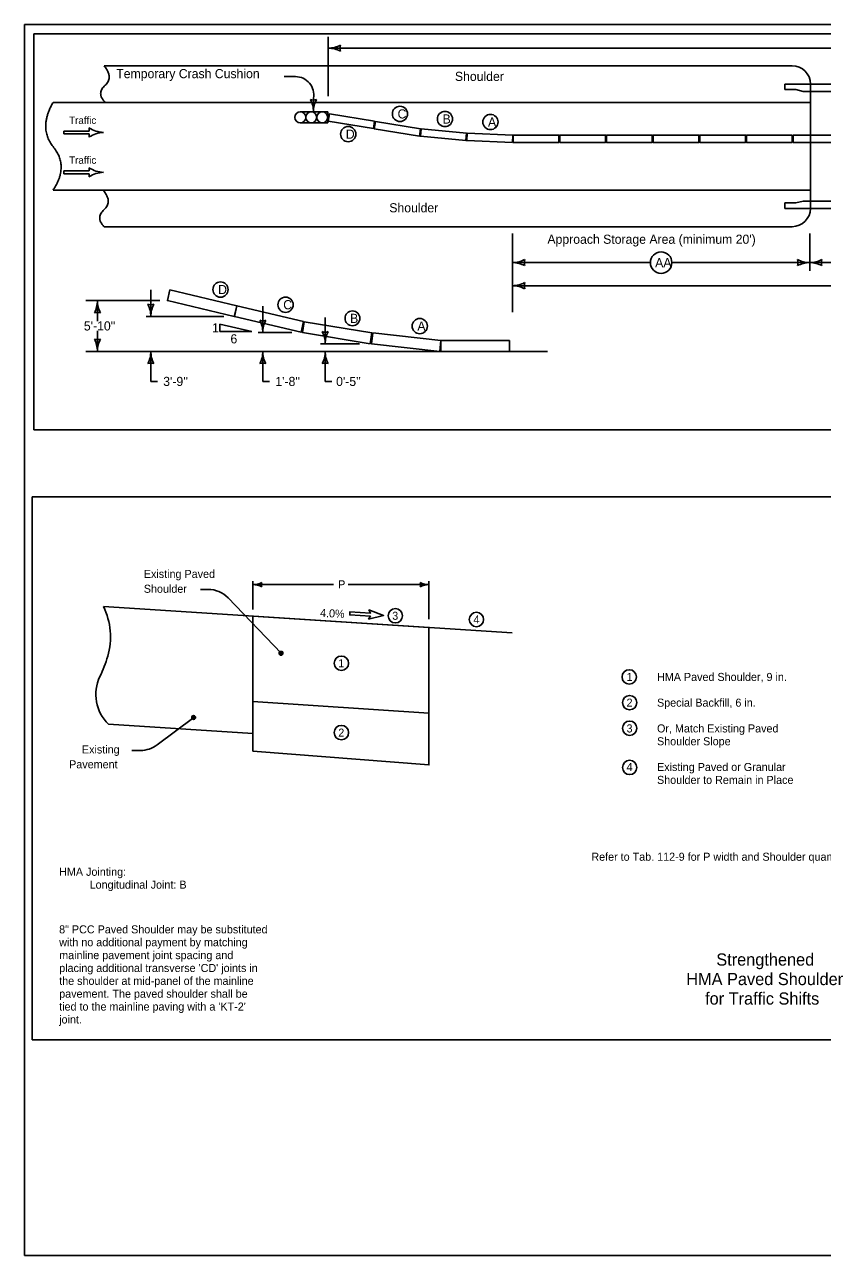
# Model space of a CAD drawing. Extents: x 10133 to 81668, y 7924 to 12229.
# Drawn here: x 13733 to 15041, y 7924 to 9944 of the extents above; entities that cross this region are included whole.
import ezdxf

# ---------------------------------------------------------------- set-up
doc = ezdxf.new("R2010")
doc.units = 0
for name, color, linetype in [('dsnTextFinalPlan', 7, 'Continuous'), ('Level 11', 7, 'Continuous'), ('Level 14', 7, 'Continuous'), ('Level 2', 7, 'Continuous'), ('Level 20', 7, 'Continuous'), ('Level 8', 7, 'Continuous'), ('Level 9', 7, 'Continuous'), ('SheetBorder', 7, 'Continuous'), ('SheetText', 7, 'Continuous')]:
    doc.layers.add(name, color=color, linetype=linetype)

msp = doc.modelspace()

# ---------------------------------------------------------------- linework, layer by layer
at = {"layer": 'dsnTextFinalPlan'}
for p, q in [((14395.5, 8954.6), (14107, 8973.3)), ((14107, 8973.3), (14107, 8832.9)), ((14395.5, 8814.2), (14395.5, 8954.6)), ((14107, 8832.9), (14395.5, 8814.2))]:
    msp.add_line(p, q, dxfattribs=at)
msp.add_circle((14252, 8895.9), 11.8, dxfattribs=at)
at = {"layer": 'Level 11'}
for p, q in [((14230.5, 9924.1), (14230.5, 9826.6)), ((14230.5, 9905.4), (15109, 9905.4)), ((13862.8, 9876.4), (14991.3, 9876.4)), ((14176.7, 9858.7), (14158, 9858.7)), ((15021.3, 9846.4), (14979.3, 9846.4)), ((14979.3, 9846.4), (14979.3, 9837.4)), ((14979.3, 9837.4), (14997.3, 9837.4)), ((15009.3, 9834.4), (14997.3, 9837.4)), ((15021.3, 9846.4), (15021.3, 9642.4)), ((15021.3, 9846.4), (15167.3, 9846.4)), ((14206.2, 9823.4), (14206.2, 9800.9)), ((15021.3, 9834.4), (15009.3, 9834.4)), ((15021.3, 9834.4), (15167.3, 9834.4)), ((13779.2, 9816.4), (15021.3, 9816.4)), ((14184.6, 9800.9), (14229.6, 9800.9)), ((14229.6, 9800.9), (14229.6, 9782.8)), ((14229.6, 9782.8), (14184.6, 9782.8)), ((14228.4, 9788.6), (14229.7, 9788.3)), ((14230.1, 9784.9), (14230.1, 9784.9)), ((13838.1, 9769.3), (13796.8, 9769.3)), ((13796.8, 9769.3), (13796.8, 9764.8)), ((13796.8, 9764.8), (13838.1, 9764.8)), ((13838.1, 9774.5), (13838.1, 9769.3)), ((13838.1, 9764.8), (13838.1, 9759.5)), ((13862, 9767), (13862, 9767)), ((13838.1, 9703.8), (13796.8, 9703.8)), ((13796.8, 9703.8), (13796.8, 9699.3)), ((13796.8, 9699.3), (13838.1, 9699.3)), ((13838.1, 9709.1), (13838.1, 9703.8)), ((13838.1, 9699.3), (13838.1, 9694.1)), ((13862, 9701.6), (13862, 9701.6)), ((13779.2, 9672.4), (15021.3, 9672.4)), ((14979.3, 9651.4), (14997.3, 9651.4)), ((14979.3, 9642.4), (14979.3, 9651.4)), ((15021.3, 9642.4), (14979.3, 9642.4)), ((15009.3, 9654.4), (14997.3, 9651.4)), ((15021.3, 9654.4), (15009.3, 9654.4)), ((15021.3, 9654.4), (15167.3, 9654.4)), ((15021.3, 9642.4), (15167.3, 9642.4)), ((13862.8, 9612.4), (14991.3, 9612.4)), ((14532.6, 9601.2), (14532.6, 9472)), ((15020.1, 9601.2), (15020.1, 9539.9)), ((14532.6, 9553.4), (14758.7, 9553.4)), ((14794, 9553.4), (15020.1, 9553.4)), ((15020.1, 9553.4), (15163.3, 9553.4)), ((14532.6, 9515.5), (15123.4, 9515.5)), ((13939.5, 9508.5), (13939.5, 9465)), ((13954.1, 9491), (13832.9, 9491)), ((13851.9, 9491), (13851.9, 9457.5)), ((14123.1, 9482.1), (14123.1, 9438.6)), ((14059, 9465), (13931.8, 9465)), ((14225.5, 9463.5), (14225.5, 9420.1)), ((13851.9, 9441.2), (13851.9, 9407.7)), ((14170.9, 9438.6), (14115.3, 9438.6)), ((14281.8, 9420.1), (14217.7, 9420.1)), ((14590.3, 9407.7), (13832.9, 9407.7)), ((13939.5, 9407.7), (13939.5, 9358.5)), ((14123.1, 9407.7), (14123.1, 9358.5)), ((14225.5, 9407.7), (14225.5, 9380.8)), ((14225.5, 9380.8), (14225.5, 9358.5)), ((13939.5, 9358.5), (13950.7, 9358.5)), ((14123.1, 9358.5), (14134.3, 9358.5)), ((14225.5, 9358.5), (14236.6, 9358.5))]:
    msp.add_line(p, q, dxfattribs=at)
for points in [[(14306.4, 9785.3), (14232.4, 9797.4), (14230.5, 9785.6), (14304.5, 9773.4)], [(14381.9, 9772.9), (14307.9, 9785), (14306, 9773.2), (14380, 9761)], [(14457.3, 9765.7), (14382.7, 9772.8), (14381.5, 9760.8), (14456.2, 9753.7)], [(14533.1, 9762.7), (14458.2, 9765.7), (14457.7, 9753.7), (14532.6, 9750.7)], [(14533.8, 9762.7), (14608.8, 9762.7), (14608.8, 9750.7), (14533.8, 9750.7)], [(14610.3, 9762.7), (14685.3, 9762.7), (14685.3, 9750.7), (14610.3, 9750.7)], [(14686.8, 9762.7), (14761.8, 9762.7), (14761.8, 9750.7), (14686.8, 9750.7)], [(14763.3, 9762.7), (14838.3, 9762.7), (14838.3, 9750.7), (14763.3, 9750.7)], [(14839.8, 9762.7), (14914.8, 9762.7), (14914.8, 9750.7), (14839.8, 9750.7)], [(14916.3, 9762.7), (14991.3, 9762.7), (14991.3, 9750.7), (14916.3, 9750.7)], [(14992.8, 9762.7), (15067.8, 9762.7), (15067.8, 9750.7), (14992.8, 9750.7)], [(14080.3, 9482.6), (13970.9, 9508.5), (13966.7, 9491), (14076.2, 9465.1)], [(14190.1, 9456.6), (14080.6, 9482.5), (14076.5, 9465), (14186, 9439.1)], [(14302.2, 9437.9), (14191.2, 9456.4), (14188.3, 9438.6), (14299.2, 9420.2)], [(14415.3, 9425.6), (14303.5, 9437.9), (14301.5, 9420.1), (14413.3, 9407.7)], [(14527.8, 9425.7), (14415.3, 9425.7), (14415.3, 9407.7), (14527.8, 9407.7)]]:
    msp.add_lwpolyline(points, close=True, dxfattribs=at)
for centre, radius in [((14184.6, 9791.8), 9), ((14184.6, 9791.8), 9), ((14202.6, 9791.8), 9), ((14202.6, 9791.8), 9), ((14220.6, 9791.8), 9), ((14220.6, 9791.8), 9), ((14348.1, 9797.5), 12.5), ((14421.9, 9789.1), 12.5), ((14263.2, 9764.3), 12.5), ((14496.4, 9784.2), 12.5), ((14776.4, 9553.4), 17.6), ((14053.8, 9509.2), 12.5), ((14160.5, 9484.3), 12.5), ((14270.2, 9461.9), 12.2), ((14380.5, 9449.2), 12.5)]:
    msp.add_circle(centre, radius, dxfattribs=at)
for centre, radius, start, end in [((14230.5, 9947.9), 42.5, 270, 298.0725), ((14230.5, 9862.9), 42.5, 61.9275, 90), ((14266.1, 9905.4), 16.4, 162.2666, 197.7334), ((14176.7, 9828.7), 30, 349.6463, 90), ((14991.3, 9846.4), 30, 0, 90), ((14206.2, 9836.5), 16.4, 252.2666, 287.7333), ((14163.7, 9800.9), 42.5, 360, 28.0725), ((14248.7, 9800.9), 42.5, 151.9275, 180), ((13864, 9815.4), 48.4, 237.618, 267.648), ((13864, 9718.7), 48.4, 92.352, 122.382), ((13864, 9749.9), 48.4, 237.618, 267.648), ((13864, 9653.3), 48.4, 92.352, 122.382), ((14991.3, 9642.4), 30, 270, 360), ((14532.6, 9595.9), 42.5, 270, 298.0725), ((14568.3, 9553.4), 16.4, 162.2666, 197.7334), ((14984.5, 9553.4), 16.4, 342.2666, 17.7333), ((15020.1, 9595.9), 42.5, 241.9275, 270), ((15020.1, 9595.9), 42.5, 270, 298.0725), ((15055.8, 9553.4), 16.4, 162.2666, 197.7334), ((14532.6, 9510.9), 42.5, 61.9275, 90), ((15020.1, 9510.9), 42.5, 90, 118.0725), ((15020.1, 9510.9), 42.5, 61.9275, 90), ((14532.6, 9558), 42.5, 270, 298.0725), ((14532.6, 9473), 42.5, 61.9275, 90), ((14568.3, 9515.5), 16.4, 162.2666, 197.7334), ((13809.4, 9491), 42.5, 331.9275, 0), ((13894.4, 9491), 42.5, 180, 208.0725), ((13939.5, 9500.7), 16.4, 252.2666, 287.7334), ((13897, 9465), 42.5, 0, 28.0725), ((13982, 9465), 42.5, 151.9275, 180), ((13851.9, 9455.4), 16.4, 72.2666, 107.7334), ((14123.1, 9474.3), 16.4, 252.2666, 287.7334), ((14080.6, 9438.6), 42.5, 0, 28.0725), ((14165.6, 9438.6), 42.5, 151.9275, 180), ((14225.5, 9455.7), 16.4, 252.2666, 287.7334), ((14183, 9420.1), 42.5, 0, 28.0725), ((14268, 9420.1), 42.5, 151.9275, 180), ((13851.9, 9443.4), 16.4, 252.2666, 287.7334), ((13809.4, 9407.7), 42.5, 0, 28.0725), ((13894.4, 9407.7), 42.5, 151.9275, 180), ((13897, 9407.7), 42.5, 331.9275, 0), ((13982, 9407.7), 42.5, 180, 208.0725), ((14080.6, 9407.7), 42.5, 331.9275, 0), ((14165.6, 9407.7), 42.5, 180, 208.0725), ((14183, 9407.7), 42.5, 331.9275, 0), ((14268, 9407.7), 42.5, 180, 208.0725), ((13939.5, 9372.1), 16.4, 72.2666, 107.7334), ((14123.1, 9372.1), 16.4, 72.2666, 107.7334), ((14225.5, 9372.1), 16.4, 72.2666, 107.7334)]:
    msp.add_arc(centre, radius, start, end, dxfattribs=at)
for points in [[(13862.8, 9876.4), (13878.9, 9857.1), (13850, 9831.5), (13864.4, 9816.5)], [(13779.2, 9816.4), (13754.6, 9773.8), (13805.3, 9711.6), (13779.2, 9672.4)], [(13861.2, 9672.4), (13877.3, 9653.1), (13848.4, 9627.5), (13862.8, 9612.4)]]:
    msp.add_open_spline(points, degree=2, dxfattribs=at)
at = {"layer": 'Level 14'}
msp.add_lwpolyline([(13745, 9169.2), (15258.4, 9169.2), (15258.4, 8277.8), (13745, 8277.8)], close=True, dxfattribs=at)
at = {"layer": 'Level 2'}
for p, q in [((14105.1, 9440.1), (14052.5, 9452.5)), ((14052.5, 9452.5), (14052.5, 9440.1)), ((14052.5, 9440.1), (14105.1, 9440.1))]:
    msp.add_line(p, q, dxfattribs=at)
at = {"layer": 'Level 20'}
msp.add_line((13747.5, 9929), (13747.5, 9929), dxfattribs=at)
at = {"layer": 'Level 8'}
for p, q in [((13747.5, 9929), (16852.5, 9929)), ((13747.5, 9279), (13747.5, 9929))]:
    msp.add_line(p, q, dxfattribs=at)
at = {"layer": 'Level 9'}
msp.add_line((16852.5, 9279), (13747.5, 9279), dxfattribs=at)
at = {"layer": 'SheetBorder'}
msp.add_lwpolyline([(13732.5, 9944), (16867.5, 9944), (16867.5, 7924), (13732.5, 7924)], close=True, dxfattribs=at)
at = {"layer": 'SheetText'}
for p, q in [((14107, 8984.2), (14107, 9030.4)), ((14395.5, 8968.1), (14395.5, 9030.4)), ((14020.9, 9017), (14033.6, 9017)), ((14107, 9024.9), (14239.3, 9024.9)), ((14107.1, 9024.9), (14120.9, 9024.9)), ((14263.2, 9024.9), (14395.5, 9024.9)), ((14395.5, 9024.9), (14381.7, 9024.9)), ((13861.7, 8989.1), (14532, 8945.8)), ((14066.1, 9003.2), (14153.2, 8912.4)), ((14107, 8832.9), (14395.5, 8814.2)), ((13869.8, 8795.8), (14107, 8780.5)), ((13949.9, 8762), (14009.9, 8807)), ((13922.4, 8752.7), (13908.4, 8752.7))]:
    msp.add_line(p, q, dxfattribs=at)
for points in [[(14120.6, 9022.3), (14120.1, 9024.9), (14120.6, 9027.5), (14117.5, 9026), (14112.6, 9024.9), (14117.9, 9023.6), (14120.2, 9022.6), (14119.6, 9024.9), (14119.8, 9026.5), (14117.8, 9025.6), (14115.1, 9024.9), (14118, 9024), (14119.5, 9023.5), (14119.2, 9025.7), (14117.2, 9024.9), (14118.8, 9024.4), (14118.8, 9025.1), (14118.1, 9024.9)], [(14382, 9027.4), (14382.5, 9024.8), (14382, 9022.2), (14385.1, 9023.7), (14390, 9024.8), (14384.7, 9026.1), (14382.4, 9027.1), (14383, 9024.8), (14382.8, 9023.2), (14384.8, 9024.1), (14387.5, 9024.8), (14384.6, 9025.7), (14383.1, 9026.2), (14383.4, 9024), (14385.4, 9024.8), (14383.8, 9025.3), (14383.8, 9024.6), (14384.5, 9024.8)], [(14107, 8973.5), (14107, 8751.6), (14395.5, 8729), (14395.5, 8954.6)], [(14155.2, 8914.1), (14154.2, 8914.5), (14152.6, 8915.3), (14151.2, 8914.3), (14150.3, 8913.1), (14150.1, 8911.4), (14151.3, 8910.4), (14152.7, 8909.4), (14154.2, 8909.8), (14155.3, 8910.7), (14155.8, 8912.6), (14155.1, 8913.6), (14153.6, 8914.5), (14151.9, 8914.7), (14150.8, 8913.5), (14150.7, 8911.9), (14151.6, 8910.7), (14153, 8909.8), (14153.9, 8910.3), (14154.9, 8910.8), (14155.3, 8912.4), (14154.5, 8913.2), (14153.3, 8914), (14152.1, 8914.2), (14151.5, 8912.8), (14151.6, 8911.5), (14152.6, 8910.5), (14153.3, 8910.8), (14154.3, 8911.1), (14154.5, 8912.3), (14154, 8913.2), (14153, 8913.5), (14152.2, 8912.9), (14152.1, 8912), (14152.6, 8911.2), (14153.1, 8911.1), (14153.7, 8911.3), (14154, 8912.3), (14153.6, 8912.8), (14152.9, 8913), (14152.6, 8912.5), (14152.7, 8912), (14153.1, 8911.5), (14153.4, 8911.8), (14153.2, 8912.4)], [(14011.9, 8808.7), (14010.8, 8809.1), (14009.3, 8809.9), (14007.9, 8808.9), (14007, 8807.7), (14006.8, 8806), (14008, 8805), (14009.3, 8804), (14010.8, 8804.3), (14011.9, 8805.2), (14012.5, 8807.2), (14011.8, 8808.2), (14010.3, 8809), (14008.6, 8809.3), (14007.5, 8808.1), (14007.4, 8806.5), (14008.3, 8805.3), (14009.7, 8804.4), (14010.6, 8804.9), (14011.6, 8805.4), (14012, 8806.9), (14011.1, 8807.8), (14010, 8808.6), (14008.7, 8808.7), (14008.1, 8807.4), (14008.3, 8806.1), (14009.2, 8805.1), (14010, 8805.4), (14010.9, 8805.7), (14011.2, 8806.9), (14010.7, 8807.8), (14009.7, 8808.1), (14008.9, 8807.4), (14008.7, 8806.6), (14009.2, 8805.7), (14009.8, 8805.7), (14010.4, 8805.9), (14010.6, 8806.8), (14010.3, 8807.4), (14009.6, 8807.6), (14009.2, 8807.1), (14009.3, 8806.5), (14009.8, 8806.1), (14010.1, 8806.4), (14009.9, 8807)]]:
    msp.add_lwpolyline(points, dxfattribs=at)
msp.add_lwpolyline([(14296.3, 8968.2), (14321.3, 8974.4), (14297.2, 8983.4), (14299.8, 8978.2), (14266, 8980.4), (14265.6, 8975.3), (14299.5, 8973.1)], close=True, dxfattribs=at)
for centre, radius in [((14340.5, 8973.8), 11.8), ((14473.5, 8967.7), 11.8), ((14153, 8912.2), 3.15), ((14252, 8895.9), 11.8), ((14724.1, 8873.4), 11.8), ((14724.8, 8831.2), 11.8), ((14009.7, 8806.8), 3.15), ((14252, 8782), 11.8), ((14724.8, 8789.2), 11.8), ((14724.8, 8724.8), 11.8)]:
    msp.add_circle(centre, radius, dxfattribs=at)
for centre, radius, start, end in [((14033.6, 8972), 45, 43.8398, 90), ((14107.1, 9055.5), 30.6, 270, 298.0725), ((14107.1, 8994.3), 30.6, 61.9275, 90), ((14132.7, 9024.9), 11.8, 162.2666, 197.7334), ((14369.9, 9024.9), 11.8, 342.2666, 17.7334), ((14395.5, 9055.5), 30.6, 241.9275, 270), ((14395.5, 8994.3), 30.6, 90, 118.0725), ((13760.4, 8939), 113, 343.6708, 26.3373), ((13656.4, 8969.5), 221.4, 334.4332, 343.6708), ((13917.6, 8844.5), 68.2, 154.4332, 225.5564), ((13922.4, 8797.7), 45, 270, 307.6187)]:
    msp.add_arc(centre, radius, start, end, dxfattribs=at)

# ---------------------------------------------------------------- texts
at = {"layer": 'Level 2'}
for s, height, p in [('Temporary Crash Cushion', 15, (13882.8, 9856.1)), ('Shoulder', 15, (14438.2, 9851.6)), ('C', 15, (14344.2, 9790)), ('Traffic', 12, (13805.5, 9781)), ('B', 15, (14418, 9781.6)), ('A', 15, (14492.5, 9776.7)), ('D', 15, (14259.3, 9756.8)), ('Traffic', 12, (13805.5, 9715.6)), ('Shoulder', 15, (14330.6, 9635.9)), ("Approach Storage Area (minimum 20')", 15, (14589.9, 9584.3)), ('AA', 15, (14766.6, 9545.9)), ('D', 15, (14049.9, 9501.7)), ('C', 15, (14156.6, 9476.8)), ("5'-10''", 15, (13829.7, 9442)), ('1', 15, (14039.9, 9438.9)), ('B', 15, (14266.3, 9454.4)), ('A', 15, (14376.6, 9441.7)), ('6', 15, (14070.1, 9420.8)), ("3'-9''", 15, (13959.8, 9350.9)), ("1'-8''", 15, (14143.7, 9350.9)), ("0'-5''", 15, (14243.4, 9350.9))]:
    msp.add_text(s, height=height, dxfattribs=at).set_placement(p)
at = {"layer": 'SheetText'}
for s, height, p in [('Existing Paved', 13.2, (13928, 9035.9)), ('P', 13.2, (14246.7, 9018.8)), ('Shoulder', 13.2, (13928, 9011.5)), ('3', 13.2, (14335.4, 8967.2)), ('4', 13.2, (14468.7, 8961.1)), ('1', 13.2, (14246.9, 8889.3)), ('1', 13.2, (14719.7, 8866.8)), ('HMA Paved Shoulder, 9 in.', 13.2, (14769.7, 8866.8)), ('2', 13.2, (14719.7, 8824.6)), ('Special Backfill, 6 in.', 13.2, (14769.7, 8824.6)), ('2', 13.2, (14246.9, 8775.4)), ('3', 13.2, (14719.7, 8782.3)), ('Or, Match Existing Paved ', 13.2, (14769.7, 8782.3)), ('Shoulder Slope', 13.2, (14769.7, 8761.2)), ('Existing', 13.2, (13826.5, 8747.8)), ('Pavement', 13.2, (13805.5, 8723.4)), ('4', 13.2, (14719.7, 8719)), ('Existing Paved or Granular ', 13.2, (14769.7, 8719)), ('Shoulder to Remain in Place', 13.2, (14769.7, 8697.8)), ('Refer to Tab. 112-9 for P width and Shoulder quantities', 13.2, (14662, 8571.7)), ('HMA Jointing:', 13.2, (13789.1, 8547)), ('Longitudinal Joint: B', 13.2, (13839.1, 8525.9)), ('8" PCC Paved Shoulder may be substituted ', 13.2, (13789.1, 8452.5)), ('with no additional payment by matching ', 13.2, (13789.2, 8431.4)), ('mainline pavement joint spacing and ', 13.2, (13789.2, 8410.2)), ('Strengthened ', 20, (14866.9, 8399.6)), ("placing additional transverse 'CD' joints in ", 13.2, (13789.2, 8389.1)), ('HMA Paved Shoulder', 20, (14817.7, 8367.6)), ('the shoulder at mid-panel of the mainline ', 13.2, (13789.2, 8368)), ('pavement. The paved shoulder shall be ', 13.2, (13789.2, 8346.9)), ('for Traffic Shifts', 20, (14848.5, 8335.6)), ("tied to the mainline paving with a 'KT-2' ", 13.2, (13789.2, 8325.8)), ('joint.', 13.2, (13789.2, 8304.6))]:
    msp.add_text(s, height=height, dxfattribs=at).set_placement(p)
msp.add_text('4.0%', height=13.2, rotation=357.4961, dxfattribs=at).set_placement((14216.8, 8972))

doc.saveas('drawing.dxf')
